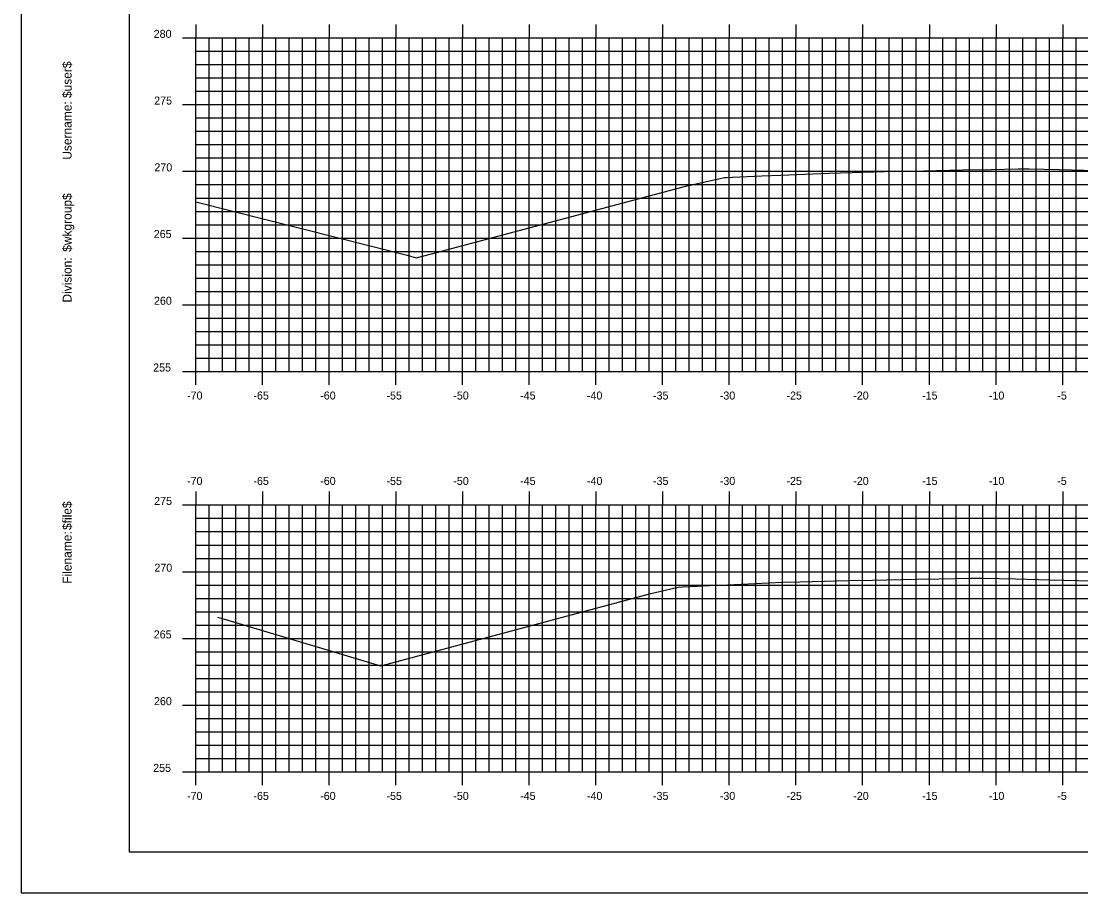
# Model space of a CAD drawing. Extents: x 1168600 to 1177589, y 610178 to 611246.
# Drawn here: x 1176530.8 to 1176610.3, y 610268.7 to 610334 of the extents above; entities that cross this region are included whole.
import ezdxf

# ---------------------------------------------------------------- set-up
doc = ezdxf.new("R2010")
doc.units = 0
for name, color, linetype in [('_Construction', 7, 'Continuous'), ('_Station Equation', 7, 'Continuous'), ('H_V ANNOTATION', 7, 'Continuous'), ('MAJOR', 7, 'Continuous'), ('MINOR', 7, 'Continuous')]:
    doc.layers.add(name, color=color, linetype=linetype)

msp = doc.modelspace()

# ---------------------------------------------------------------- linework, layer by layer
at = {"layer": '_Construction'}
for p, q in [((1176538.898, 610376.801), (1176538.898, 610271.801)), ((1176538.898, 610271.801), (1176698.898, 610271.801))]:
    msp.add_line(p, q, dxfattribs=at)
msp.add_lwpolyline([(1176530.805, 610268.742), (1176700.805, 610268.742), (1176700.805, 610378.742), (1176530.805, 610378.742)], close=True, dxfattribs=at)
at = {"layer": '_Station Equation'}
for points in [[(1176543.898, 610320.524), (1176559.735, 610316.517), (1176560.41, 610316.315), (1176561.582, 610316.63), (1176580.913, 610321.753), (1176581.004, 610321.775), (1176581.055, 610321.787), (1176581.199, 610321.818), (1176583.548, 610322.337), (1176583.7, 610322.344), (1176584.148, 610322.363), (1176586.345, 610322.455), (1176587.775, 610322.517), (1176591.354, 610322.672), (1176593.123, 610322.718), (1176596.364, 610322.805), (1176598.47, 610322.849), (1176601.374, 610322.911), (1176603.527, 610322.949), (1176605.554, 610322.987), (1176605.961, 610322.982), (1176606.384, 610322.977), (1176608.648, 610322.928), (1176611.394, 610322.872)], [(1176545.514, 610289.388), (1176546.054, 610289.251), (1176555.987, 610286.275), (1176557.751, 610285.744), (1176557.783, 610285.736), (1176557.869, 610285.763), (1176578.017, 610291.175), (1176578.018, 610291.175), (1176578.018, 610291.175), (1176578.018, 610291.175), (1176578.019, 610291.175), (1176580.056, 610291.648), (1176580.418, 610291.663), (1176581.482, 610291.716), (1176582.855, 610291.785), (1176583.763, 610291.825), (1176587.869, 610292.005), (1176589.194, 610292.039), (1176592.884, 610292.135), (1176594.623, 610292.173), (1176597.898, 610292.246), (1176599.626, 610292.278), (1176602.009, 610292.323), (1176602.441, 610292.317), (1176602.913, 610292.31), (1176605.37, 610292.256), (1176607.927, 610292.2), (1176610.032, 610292.148), (1176612.941, 610292.075)]]:
    msp.add_lwpolyline(points, dxfattribs=at)
at = {"layer": 'MAJOR'}
for p, q in [((1176543.898, 610333.803), (1176543.898, 610332.801)), ((1176548.898, 610333.803), (1176548.898, 610332.801)), ((1176553.898, 610333.803), (1176553.898, 610332.801)), ((1176558.898, 610333.803), (1176558.898, 610332.801)), ((1176563.898, 610333.803), (1176563.898, 610332.801)), ((1176568.898, 610333.803), (1176568.898, 610332.801)), ((1176573.898, 610333.803), (1176573.898, 610332.801)), ((1176578.898, 610333.803), (1176578.898, 610332.801)), ((1176583.898, 610333.803), (1176583.898, 610332.801)), ((1176588.898, 610333.803), (1176588.898, 610332.801)), ((1176593.898, 610333.803), (1176593.898, 610332.801)), ((1176598.898, 610333.803), (1176598.898, 610332.801)), ((1176603.898, 610333.803), (1176603.898, 610332.801)), ((1176608.898, 610333.803), (1176608.898, 610332.801)), ((1176542.896, 610332.801), (1176543.898, 610332.801)), ((1176543.898, 610332.801), (1176683.898, 610332.801)), ((1176543.898, 610307.801), (1176543.898, 610332.801)), ((1176543.898, 610307.801), (1176543.898, 610332.801)), ((1176543.898, 610332.801), (1176683.898, 610332.801)), ((1176548.898, 610307.801), (1176548.898, 610332.801)), ((1176553.898, 610307.801), (1176553.898, 610332.801)), ((1176558.898, 610307.801), (1176558.898, 610332.801)), ((1176563.898, 610307.801), (1176563.898, 610332.801)), ((1176568.898, 610307.801), (1176568.898, 610332.801)), ((1176573.898, 610307.801), (1176573.898, 610332.801)), ((1176578.898, 610307.801), (1176578.898, 610332.801)), ((1176583.898, 610307.801), (1176583.898, 610332.801)), ((1176588.898, 610307.801), (1176588.898, 610332.801)), ((1176593.898, 610307.801), (1176593.898, 610332.801)), ((1176598.898, 610307.801), (1176598.898, 610332.801)), ((1176603.898, 610307.801), (1176603.898, 610332.801)), ((1176608.898, 610307.801), (1176608.898, 610332.801)), ((1176542.896, 610327.801), (1176543.898, 610327.801)), ((1176543.898, 610327.801), (1176683.898, 610327.801)), ((1176542.896, 610322.801), (1176543.898, 610322.801)), ((1176543.898, 610322.801), (1176683.898, 610322.801)), ((1176542.896, 610317.801), (1176543.898, 610317.801)), ((1176543.898, 610317.801), (1176683.898, 610317.801)), ((1176542.896, 610312.801), (1176543.898, 610312.801)), ((1176543.898, 610312.801), (1176683.898, 610312.801)), ((1176542.896, 610307.801), (1176543.898, 610307.801)), ((1176543.898, 610307.801), (1176683.898, 610307.801)), ((1176543.898, 610307.801), (1176683.898, 610307.801)), ((1176543.898, 610306.799), (1176543.898, 610307.801)), ((1176548.898, 610306.799), (1176548.898, 610307.801)), ((1176553.898, 610306.799), (1176553.898, 610307.801)), ((1176558.898, 610306.799), (1176558.898, 610307.801)), ((1176563.898, 610306.799), (1176563.898, 610307.801)), ((1176568.898, 610306.799), (1176568.898, 610307.801)), ((1176573.898, 610306.799), (1176573.898, 610307.801)), ((1176578.898, 610306.799), (1176578.898, 610307.801)), ((1176583.898, 610306.799), (1176583.898, 610307.801)), ((1176588.898, 610306.799), (1176588.898, 610307.801)), ((1176593.898, 610306.799), (1176593.898, 610307.801)), ((1176598.898, 610306.799), (1176598.898, 610307.801)), ((1176603.898, 610306.799), (1176603.898, 610307.801)), ((1176608.898, 610306.799), (1176608.898, 610307.801)), ((1176543.898, 610298.803), (1176543.898, 610297.801)), ((1176548.898, 610298.803), (1176548.898, 610297.801)), ((1176553.898, 610298.803), (1176553.898, 610297.801)), ((1176558.898, 610298.803), (1176558.898, 610297.801)), ((1176563.898, 610298.803), (1176563.898, 610297.801)), ((1176568.898, 610298.803), (1176568.898, 610297.801)), ((1176573.898, 610298.803), (1176573.898, 610297.801)), ((1176578.898, 610298.803), (1176578.898, 610297.801)), ((1176583.898, 610298.803), (1176583.898, 610297.801)), ((1176588.898, 610298.803), (1176588.898, 610297.801)), ((1176593.898, 610298.803), (1176593.898, 610297.801)), ((1176598.898, 610298.803), (1176598.898, 610297.801)), ((1176603.898, 610298.803), (1176603.898, 610297.801)), ((1176608.898, 610298.803), (1176608.898, 610297.801)), ((1176542.896, 610297.801), (1176543.898, 610297.801)), ((1176543.898, 610297.801), (1176683.898, 610297.801)), ((1176543.898, 610277.801), (1176543.898, 610297.801)), ((1176543.898, 610277.801), (1176543.898, 610297.801)), ((1176543.898, 610297.801), (1176683.898, 610297.801)), ((1176548.898, 610277.801), (1176548.898, 610297.801)), ((1176553.898, 610277.801), (1176553.898, 610297.801)), ((1176558.898, 610277.801), (1176558.898, 610297.801)), ((1176563.898, 610277.801), (1176563.898, 610297.801)), ((1176568.898, 610277.801), (1176568.898, 610297.801)), ((1176573.898, 610277.801), (1176573.898, 610297.801)), ((1176578.898, 610277.801), (1176578.898, 610297.801)), ((1176583.898, 610277.801), (1176583.898, 610297.801)), ((1176588.898, 610277.801), (1176588.898, 610297.801)), ((1176593.898, 610277.801), (1176593.898, 610297.801)), ((1176598.898, 610277.801), (1176598.898, 610297.801)), ((1176603.898, 610277.801), (1176603.898, 610297.801)), ((1176608.898, 610277.801), (1176608.898, 610297.801)), ((1176542.896, 610292.801), (1176543.898, 610292.801)), ((1176543.898, 610292.801), (1176683.898, 610292.801)), ((1176542.896, 610287.801), (1176543.898, 610287.801)), ((1176543.898, 610287.801), (1176683.898, 610287.801)), ((1176542.896, 610282.801), (1176543.898, 610282.801)), ((1176543.898, 610282.801), (1176683.898, 610282.801)), ((1176542.896, 610277.801), (1176543.898, 610277.801)), ((1176543.898, 610277.801), (1176683.898, 610277.801)), ((1176543.898, 610277.801), (1176683.898, 610277.801)), ((1176543.898, 610276.799), (1176543.898, 610277.801)), ((1176548.898, 610276.799), (1176548.898, 610277.801)), ((1176553.898, 610276.799), (1176553.898, 610277.801)), ((1176558.898, 610276.799), (1176558.898, 610277.801)), ((1176563.898, 610276.799), (1176563.898, 610277.801)), ((1176568.898, 610276.799), (1176568.898, 610277.801)), ((1176573.898, 610276.799), (1176573.898, 610277.801)), ((1176578.898, 610276.799), (1176578.898, 610277.801)), ((1176583.898, 610276.799), (1176583.898, 610277.801)), ((1176588.898, 610276.799), (1176588.898, 610277.801)), ((1176593.898, 610276.799), (1176593.898, 610277.801)), ((1176598.898, 610276.799), (1176598.898, 610277.801)), ((1176603.898, 610276.799), (1176603.898, 610277.801)), ((1176608.898, 610276.799), (1176608.898, 610277.801))]:
    msp.add_line(p, q, dxfattribs=at)
at = {"layer": 'MINOR'}
for p, q in [((1176544.898, 610307.801), (1176544.898, 610332.801)), ((1176545.898, 610307.801), (1176545.898, 610332.801)), ((1176546.898, 610307.801), (1176546.898, 610332.801)), ((1176547.898, 610307.801), (1176547.898, 610332.801)), ((1176549.898, 610307.801), (1176549.898, 610332.801)), ((1176550.898, 610307.801), (1176550.898, 610332.801)), ((1176551.898, 610307.801), (1176551.898, 610332.801)), ((1176552.898, 610307.801), (1176552.898, 610332.801)), ((1176554.898, 610307.801), (1176554.898, 610332.801)), ((1176555.898, 610307.801), (1176555.898, 610332.801)), ((1176556.898, 610307.801), (1176556.898, 610332.801)), ((1176557.898, 610307.801), (1176557.898, 610332.801)), ((1176559.898, 610307.801), (1176559.898, 610332.801)), ((1176560.898, 610307.801), (1176560.898, 610332.801)), ((1176561.898, 610307.801), (1176561.898, 610332.801)), ((1176562.898, 610307.801), (1176562.898, 610332.801)), ((1176564.898, 610307.801), (1176564.898, 610332.801)), ((1176565.898, 610307.801), (1176565.898, 610332.801)), ((1176566.898, 610307.801), (1176566.898, 610332.801)), ((1176567.898, 610307.801), (1176567.898, 610332.801)), ((1176569.898, 610307.801), (1176569.898, 610332.801)), ((1176570.898, 610307.801), (1176570.898, 610332.801)), ((1176571.898, 610307.801), (1176571.898, 610332.801)), ((1176572.898, 610307.801), (1176572.898, 610332.801)), ((1176574.898, 610307.801), (1176574.898, 610332.801)), ((1176575.898, 610307.801), (1176575.898, 610332.801)), ((1176576.898, 610307.801), (1176576.898, 610332.801)), ((1176577.898, 610307.801), (1176577.898, 610332.801)), ((1176579.898, 610307.801), (1176579.898, 610332.801)), ((1176580.898, 610307.801), (1176580.898, 610332.801)), ((1176581.898, 610307.801), (1176581.898, 610332.801)), ((1176582.898, 610307.801), (1176582.898, 610332.801)), ((1176584.898, 610307.801), (1176584.898, 610332.801)), ((1176585.898, 610307.801), (1176585.898, 610332.801)), ((1176586.898, 610307.801), (1176586.898, 610332.801)), ((1176587.898, 610307.801), (1176587.898, 610332.801)), ((1176589.898, 610307.801), (1176589.898, 610332.801)), ((1176590.898, 610307.801), (1176590.898, 610332.801)), ((1176591.898, 610307.801), (1176591.898, 610332.801)), ((1176592.898, 610307.801), (1176592.898, 610332.801)), ((1176594.898, 610307.801), (1176594.898, 610332.801)), ((1176595.898, 610307.801), (1176595.898, 610332.801)), ((1176596.898, 610307.801), (1176596.898, 610332.801)), ((1176597.898, 610307.801), (1176597.898, 610332.801)), ((1176599.898, 610307.801), (1176599.898, 610332.801)), ((1176600.898, 610307.801), (1176600.898, 610332.801)), ((1176601.898, 610307.801), (1176601.898, 610332.801)), ((1176602.898, 610307.801), (1176602.898, 610332.801)), ((1176604.898, 610307.801), (1176604.898, 610332.801)), ((1176605.898, 610307.801), (1176605.898, 610332.801)), ((1176606.898, 610307.801), (1176606.898, 610332.801)), ((1176607.898, 610307.801), (1176607.898, 610332.801)), ((1176609.898, 610307.801), (1176609.898, 610332.801)), ((1176543.898, 610331.801), (1176683.898, 610331.801)), ((1176543.898, 610331.801), (1176544.9, 610331.801)), ((1176543.898, 610330.801), (1176683.898, 610330.801)), ((1176543.898, 610330.801), (1176544.9, 610330.801)), ((1176543.898, 610329.801), (1176683.898, 610329.801)), ((1176543.898, 610329.801), (1176544.9, 610329.801)), ((1176543.898, 610328.801), (1176683.898, 610328.801)), ((1176543.898, 610328.801), (1176544.9, 610328.801)), ((1176543.898, 610326.801), (1176683.898, 610326.801)), ((1176543.898, 610326.801), (1176544.9, 610326.801)), ((1176543.898, 610325.801), (1176683.898, 610325.801)), ((1176543.898, 610325.801), (1176544.9, 610325.801)), ((1176543.898, 610324.801), (1176683.898, 610324.801)), ((1176543.898, 610324.801), (1176544.9, 610324.801)), ((1176543.898, 610323.801), (1176683.898, 610323.801)), ((1176543.898, 610323.801), (1176544.9, 610323.801)), ((1176543.898, 610321.801), (1176683.898, 610321.801)), ((1176543.898, 610321.801), (1176544.9, 610321.801)), ((1176543.898, 610320.801), (1176683.898, 610320.801)), ((1176543.898, 610320.801), (1176544.9, 610320.801)), ((1176543.898, 610319.801), (1176683.898, 610319.801)), ((1176543.898, 610319.801), (1176544.9, 610319.801)), ((1176543.898, 610318.801), (1176683.898, 610318.801)), ((1176543.898, 610318.801), (1176544.9, 610318.801)), ((1176543.898, 610316.801), (1176683.898, 610316.801)), ((1176543.898, 610316.801), (1176544.9, 610316.801)), ((1176543.898, 610315.801), (1176683.898, 610315.801)), ((1176543.898, 610315.801), (1176544.9, 610315.801)), ((1176543.898, 610314.801), (1176683.898, 610314.801)), ((1176543.898, 610314.801), (1176544.9, 610314.801)), ((1176543.898, 610313.801), (1176683.898, 610313.801)), ((1176543.898, 610313.801), (1176544.9, 610313.801)), ((1176543.898, 610311.801), (1176683.898, 610311.801)), ((1176543.898, 610311.801), (1176544.9, 610311.801)), ((1176543.898, 610310.801), (1176683.898, 610310.801)), ((1176543.898, 610310.801), (1176544.9, 610310.801)), ((1176543.898, 610309.801), (1176683.898, 610309.801)), ((1176543.898, 610309.801), (1176544.9, 610309.801)), ((1176543.898, 610308.801), (1176683.898, 610308.801)), ((1176543.898, 610308.801), (1176544.9, 610308.801)), ((1176544.898, 610277.801), (1176544.898, 610297.801)), ((1176545.898, 610277.801), (1176545.898, 610297.801)), ((1176546.898, 610277.801), (1176546.898, 610297.801)), ((1176547.898, 610277.801), (1176547.898, 610297.801)), ((1176549.898, 610277.801), (1176549.898, 610297.801)), ((1176550.898, 610277.801), (1176550.898, 610297.801)), ((1176551.898, 610277.801), (1176551.898, 610297.801)), ((1176552.898, 610277.801), (1176552.898, 610297.801)), ((1176554.898, 610277.801), (1176554.898, 610297.801)), ((1176555.898, 610277.801), (1176555.898, 610297.801)), ((1176556.898, 610277.801), (1176556.898, 610297.801)), ((1176557.898, 610277.801), (1176557.898, 610297.801)), ((1176559.898, 610277.801), (1176559.898, 610297.801)), ((1176560.898, 610277.801), (1176560.898, 610297.801)), ((1176561.898, 610277.801), (1176561.898, 610297.801)), ((1176562.898, 610277.801), (1176562.898, 610297.801)), ((1176564.898, 610277.801), (1176564.898, 610297.801)), ((1176565.898, 610277.801), (1176565.898, 610297.801)), ((1176566.898, 610277.801), (1176566.898, 610297.801)), ((1176567.898, 610277.801), (1176567.898, 610297.801)), ((1176569.898, 610277.801), (1176569.898, 610297.801)), ((1176570.898, 610277.801), (1176570.898, 610297.801)), ((1176571.898, 610277.801), (1176571.898, 610297.801)), ((1176572.898, 610277.801), (1176572.898, 610297.801)), ((1176574.898, 610277.801), (1176574.898, 610297.801)), ((1176575.898, 610277.801), (1176575.898, 610297.801)), ((1176576.898, 610277.801), (1176576.898, 610297.801)), ((1176577.898, 610277.801), (1176577.898, 610297.801)), ((1176579.898, 610277.801), (1176579.898, 610297.801)), ((1176580.898, 610277.801), (1176580.898, 610297.801)), ((1176581.898, 610277.801), (1176581.898, 610297.801)), ((1176582.898, 610277.801), (1176582.898, 610297.801)), ((1176584.898, 610277.801), (1176584.898, 610297.801)), ((1176585.898, 610277.801), (1176585.898, 610297.801)), ((1176586.898, 610277.801), (1176586.898, 610297.801)), ((1176587.898, 610277.801), (1176587.898, 610297.801)), ((1176589.898, 610277.801), (1176589.898, 610297.801)), ((1176590.898, 610277.801), (1176590.898, 610297.801)), ((1176591.898, 610277.801), (1176591.898, 610297.801)), ((1176592.898, 610277.801), (1176592.898, 610297.801)), ((1176594.898, 610277.801), (1176594.898, 610297.801)), ((1176595.898, 610277.801), (1176595.898, 610297.801)), ((1176596.898, 610277.801), (1176596.898, 610297.801)), ((1176597.898, 610277.801), (1176597.898, 610297.801)), ((1176599.898, 610277.801), (1176599.898, 610297.801)), ((1176600.898, 610277.801), (1176600.898, 610297.801)), ((1176601.898, 610277.801), (1176601.898, 610297.801)), ((1176602.898, 610277.801), (1176602.898, 610297.801)), ((1176604.898, 610277.801), (1176604.898, 610297.801)), ((1176605.898, 610277.801), (1176605.898, 610297.801)), ((1176606.898, 610277.801), (1176606.898, 610297.801)), ((1176607.898, 610277.801), (1176607.898, 610297.801)), ((1176609.898, 610277.801), (1176609.898, 610297.801)), ((1176543.898, 610296.801), (1176683.898, 610296.801)), ((1176543.898, 610296.801), (1176544.9, 610296.801)), ((1176543.898, 610295.801), (1176683.898, 610295.801)), ((1176543.898, 610295.801), (1176544.9, 610295.801)), ((1176543.898, 610294.801), (1176683.898, 610294.801)), ((1176543.898, 610294.801), (1176544.9, 610294.801)), ((1176543.898, 610293.801), (1176683.898, 610293.801)), ((1176543.898, 610293.801), (1176544.9, 610293.801)), ((1176543.898, 610291.801), (1176683.898, 610291.801)), ((1176543.898, 610291.801), (1176544.9, 610291.801)), ((1176543.898, 610290.801), (1176683.898, 610290.801)), ((1176543.898, 610290.801), (1176544.9, 610290.801)), ((1176543.898, 610289.801), (1176683.898, 610289.801)), ((1176543.898, 610289.801), (1176544.9, 610289.801)), ((1176543.898, 610288.801), (1176683.898, 610288.801)), ((1176543.898, 610288.801), (1176544.9, 610288.801)), ((1176543.898, 610286.801), (1176683.898, 610286.801)), ((1176543.898, 610286.801), (1176544.9, 610286.801)), ((1176543.898, 610285.801), (1176683.898, 610285.801)), ((1176543.898, 610285.801), (1176544.9, 610285.801)), ((1176543.898, 610284.801), (1176683.898, 610284.801)), ((1176543.898, 610284.801), (1176544.9, 610284.801)), ((1176543.898, 610283.801), (1176683.898, 610283.801)), ((1176543.898, 610283.801), (1176544.9, 610283.801)), ((1176543.898, 610281.801), (1176683.898, 610281.801)), ((1176543.898, 610281.801), (1176544.9, 610281.801)), ((1176543.898, 610280.801), (1176683.898, 610280.801)), ((1176543.898, 610280.801), (1176544.9, 610280.801)), ((1176543.898, 610279.801), (1176683.898, 610279.801)), ((1176543.898, 610279.801), (1176544.9, 610279.801)), ((1176543.898, 610278.801), (1176683.898, 610278.801)), ((1176543.898, 610278.801), (1176544.9, 610278.801))]:
    msp.add_line(p, q, dxfattribs=at)

# ---------------------------------------------------------------- texts
at = {"layer": '_Construction'}
for s, p in [('$user$', (1176534.583, 610328.293)), ('Username:', (1176534.583, 610323.669)), ('$wkgroup$', (1176534.583, 610316.771)), ('Division:', (1176534.583, 610312.967)), ('$file$', (1176534.583, 610295.927)), ('Filename:', (1176534.583, 610291.899))]:
    msp.add_text(s, height=0.6696, rotation=90, dxfattribs=at).set_placement(p)
at = {"layer": 'H_V ANNOTATION'}
for s, p in [('280', (1176540.739, 610332.801)), ('275', (1176540.776, 610327.801)), ('270', (1176540.792, 610322.801)), ('265', (1176540.744, 610317.801)), ('260', (1176540.76, 610312.801)), ('255', (1176540.701, 610307.801)), ('-70', (1176543.24, 610305.701)), ('-65', (1176548.216, 610305.701)), ('-60', (1176553.224, 610305.701)), ('-55', (1176558.194, 610305.701)), ('-50', (1176563.202, 610305.701)), ('-45', (1176568.216, 610305.701)), ('-40', (1176573.224, 610305.701)), ('-35', (1176578.178, 610305.701)), ('-30', (1176583.186, 610305.701)), ('-25', (1176588.183, 610305.701)), ('-20', (1176593.191, 610305.701)), ('-15', (1176598.355, 610305.701)), ('-10', (1176603.363, 610305.701)), ('-5', (1176608.489, 610305.701)), ('-70', (1176543.24, 610299.301)), ('-65', (1176548.216, 610299.301)), ('-60', (1176553.224, 610299.301)), ('-55', (1176558.194, 610299.301)), ('-50', (1176563.202, 610299.301)), ('-45', (1176568.216, 610299.301)), ('-40', (1176573.224, 610299.301)), ('-35', (1176578.178, 610299.301)), ('-30', (1176583.186, 610299.301)), ('-25', (1176588.183, 610299.301)), ('-20', (1176593.191, 610299.301)), ('-15', (1176598.355, 610299.301)), ('-10', (1176603.363, 610299.301)), ('-5', (1176608.489, 610299.301)), ('275', (1176540.776, 610297.801)), ('270', (1176540.792, 610292.801)), ('265', (1176540.744, 610287.801)), ('260', (1176540.76, 610282.801)), ('255', (1176540.701, 610277.801)), ('-70', (1176543.24, 610275.701)), ('-65', (1176548.216, 610275.701)), ('-60', (1176553.224, 610275.701)), ('-55', (1176558.194, 610275.701)), ('-50', (1176563.202, 610275.701)), ('-45', (1176568.216, 610275.701)), ('-40', (1176573.224, 610275.701)), ('-35', (1176578.178, 610275.701)), ('-30', (1176583.186, 610275.701)), ('-25', (1176588.183, 610275.701)), ('-20', (1176593.191, 610275.701)), ('-15', (1176598.355, 610275.701)), ('-10', (1176603.363, 610275.701)), ('-5', (1176608.489, 610275.701))]:
    msp.add_text(s, height=0.6, dxfattribs=at).set_placement(p)

doc.saveas('drawing.dxf')
